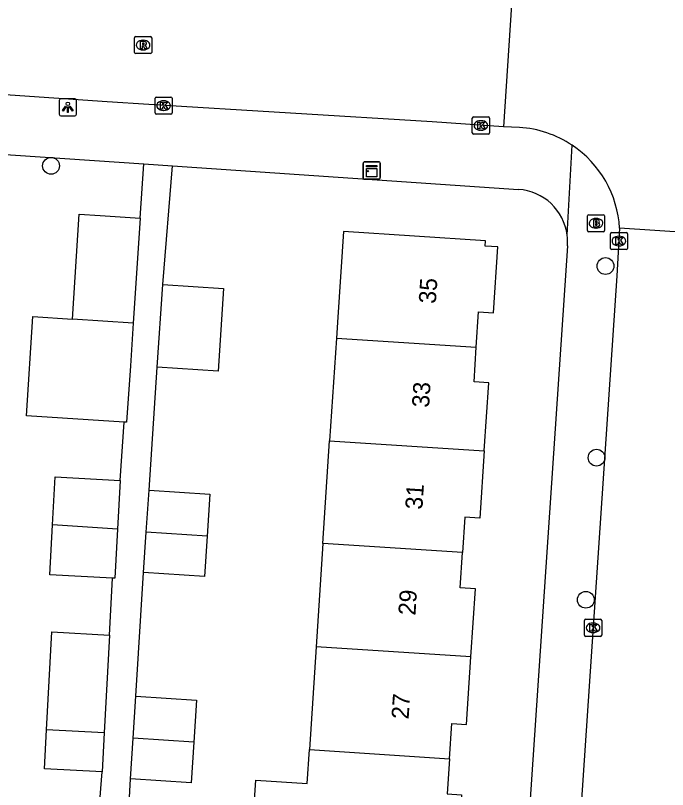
# Model space of a CAD drawing. Extents: x 161848 to 162726, y 385382 to 386521.
# Drawn here: x 162407.24 to 162445.21, y 385547.73 to 385592.78 of the extents above; entities that cross this region are included whole.
import ezdxf

# ---------------------------------------------------------------- set-up
doc = ezdxf.new("R2010")
doc.units = 0
for name, color, linetype in [('IMGEO_Boom', 7, 'Continuous'), ('IMGEO_Brandkraan', 7, 'Continuous'), ('IMGEO_Kast', 7, 'Continuous'), ('IMGEO_Kolk', 7, 'Continuous'), ('IMGEO_Lichtpunt', 7, 'Continuous'), ('IMGEO_Pand', 7, 'Continuous'), ('IMGEO_Pand_nummerreeks', 7, 'Continuous'), ('IMGEO_Rijbaan_lokaal_gesloten', 7, 'Continuous'), ('IMGEO_Rijbaan_lokaal_open', 7, 'Continuous'), ('IMGEO_Rioolput', 7, 'Continuous'), ('IMGEO_Voetpad_open', 7, 'Continuous')]:
    doc.layers.add(name, color=color, linetype=linetype)

msp = doc.modelspace()

# ---------------------------------------------------------------- linework, layer by layer
at = {"layer": 'IMGEO_Boom'}
for centre in [(162409.312, 385584.031), (162441.596, 385578.195), (162441.076, 385567.043), (162440.451, 385558.773)]:
    msp.add_circle(centre, 0.489, dxfattribs=at)
at = {"layer": 'IMGEO_Brandkraan'}
for p, q in [((162440.542, 385580.258), (162440.542, 385581.11)), ((162440.617, 385581.184), (162441.469, 385581.184)), ((162441.03, 385580.964), (162441.055, 385580.964)), ((162441.543, 385581.11), (162441.543, 385580.258)), ((162441.053, 385580.404), (162441.028, 385580.404)), ((162441.469, 385580.184), (162440.617, 385580.184))]:
    msp.add_line(p, q, dxfattribs=at)
for points in [[(162440.542, 385580.258), (162440.542, 385581.11)], [(162440.617, 385581.184), (162441.469, 385581.184)], [(162440.89, 385580.884), (162440.89, 385580.484), (162441.103, 385580.484)], [(162441.121, 385580.884), (162440.89, 385580.884)], [(162441.543, 385581.11), (162441.543, 385580.258)], [(162441.069, 385580.803), (162441.015, 385580.803), (162441.015, 385580.727)], [(162441.015, 385580.727), (162441.068, 385580.727)], [(162441.077, 385580.651), (162441.015, 385580.651), (162441.015, 385580.57)], [(162441.015, 385580.57), (162441.077, 385580.57)], [(162441.469, 385580.184), (162440.617, 385580.184)]]:
    msp.add_lwpolyline(points, dxfattribs=at)
for centre, radius, start, end in [((162440.619, 385581.108), 0.0765, 91.552, 178.448), ((162440.619, 385581.108), 0.0765, 91.552, 178.448), ((162441.125, 385580.739), 0.145, 59.4692, 91.5367), ((162441.15, 385580.786), 0.0922, 285.5137, 58.1501), ((162441.467, 385581.108), 0.0765, 1.552, 88.448), ((162441.467, 385581.108), 0.0765, 1.552, 88.448), ((162441.07, 385580.765), 0.0379, 267.8285, 90.9355), ((162441.078, 385580.61), 0.0404, 269.8759, 90.5077), ((162441.109, 385580.735), 0.251, 268.6676, 293.5347), ((162441.155, 385580.594), 0.105, 301.3115, 78.989), ((162440.619, 385580.26), 0.0765, 181.552, 268.448), ((162440.619, 385580.26), 0.0765, 181.552, 268.448), ((162441.467, 385580.26), 0.0765, 271.552, 358.448), ((162441.467, 385580.26), 0.0765, 271.552, 358.448)]:
    msp.add_arc(centre, radius, start, end, dxfattribs=at)
for centre, major_axis, ratio, start_param, end_param in [((162441.029, 385580.684), (-0.387, 0.002), 0.722429, 4.712389, 7.853982), ((162441.054, 385580.684), (-0.39, 0.002), 0.717154, 1.570796, 4.712389)]:
    msp.add_ellipse(centre, major_axis=major_axis, ratio=ratio, start_param=start_param, end_param=end_param, dxfattribs=at)
at = {"layer": 'IMGEO_Kast'}
for p, q in [((162427.478, 385583.332), (162427.478, 385584.173)), ((162427.478, 385584.173), (162427.478, 385583.332)), ((162427.553, 385584.257), (162428.394, 385584.257)), ((162428.394, 385584.257), (162427.553, 385584.257)), ((162428.478, 385584.182), (162428.478, 385583.341)), ((162428.478, 385583.341), (162428.478, 385584.182)), ((162428.403, 385583.257), (162427.562, 385583.257)), ((162427.562, 385583.257), (162428.403, 385583.257))]:
    msp.add_line(p, q, dxfattribs=at)
for points in [[(162427.673, 385584.047), (162428.273, 385584.047), (162428.273, 385583.962), (162427.673, 385583.962), (162427.673, 385584.047)], [(162427.673, 385583.872), (162428.273, 385583.872), (162428.273, 385583.383), (162427.673, 385583.383), (162427.673, 385583.872)]]:
    msp.add_lwpolyline(points, dxfattribs=at)
msp.add_circle((162427.757, 385583.721), 0.0377, dxfattribs=at)
for centre, start, end in [((162427.556, 385584.179), 92.4484, 184.2845), ((162427.556, 385584.179), 92.4484, 184.2845), ((162428.4, 385584.179), 2.4484, 94.2845), ((162428.4, 385584.179), 2.4484, 94.2845), ((162427.556, 385583.335), 182.4484, 274.2845), ((162427.556, 385583.335), 182.4484, 274.2845), ((162428.4, 385583.335), 272.4484, 4.2845), ((162428.4, 385583.335), 272.4484, 4.2845)]:
    msp.add_arc(centre, 0.0779, start, end, dxfattribs=at)
at = {"layer": 'IMGEO_Kolk'}
for p, q in [((162415.442, 385588.033), (162416.294, 385588.033)), ((162415.367, 385587.107), (162415.367, 385587.959)), ((162415.855, 385587.813), (162415.88, 385587.813)), ((162416.368, 385587.959), (162416.368, 385587.107)), ((162415.878, 385587.253), (162415.853, 385587.253)), ((162416.294, 385587.033), (162415.442, 385587.033)), ((162433.84, 385585.951), (162433.84, 385586.803)), ((162433.915, 385586.877), (162434.767, 385586.877)), ((162434.841, 385586.803), (162434.841, 385585.951)), ((162434.328, 385586.657), (162434.353, 385586.657)), ((162434.767, 385585.877), (162433.915, 385585.877)), ((162434.351, 385586.097), (162434.326, 385586.097)), ((162441.88, 385579.226), (162441.88, 385580.078)), ((162441.955, 385580.152), (162442.807, 385580.152)), ((162442.368, 385579.932), (162442.393, 385579.932)), ((162442.881, 385580.078), (162442.881, 385579.226)), ((162442.807, 385579.152), (162441.955, 385579.152)), ((162442.391, 385579.372), (162442.366, 385579.372)), ((162440.372, 385556.714), (162440.372, 385557.566)), ((162440.447, 385557.64), (162441.299, 385557.64)), ((162440.86, 385557.42), (162440.885, 385557.42)), ((162441.373, 385557.566), (162441.373, 385556.714)), ((162441.299, 385556.64), (162440.447, 385556.64)), ((162440.883, 385556.86), (162440.858, 385556.86))]:
    msp.add_line(p, q, dxfattribs=at)
for points in [[(162415.442, 385588.033), (162416.294, 385588.033)], [(162415.367, 385587.107), (162415.367, 385587.959)], [(162415.688, 385587.733), (162415.811, 385587.733), (162415.811, 385587.582), (162415.941, 385587.733), (162416.105, 385587.733), (162415.959, 385587.582), (162416.112, 385587.333), (162415.96, 385587.333), (162415.875, 385587.497), (162415.811, 385587.43), (162415.811, 385587.333), (162415.688, 385587.333), (162415.688, 385587.733)], [(162416.368, 385587.959), (162416.368, 385587.107)], [(162416.294, 385587.033), (162415.442, 385587.033)], [(162433.84, 385585.951), (162433.84, 385586.803)], [(162433.915, 385586.877), (162434.767, 385586.877)], [(162434.841, 385586.803), (162434.841, 385585.951)], [(162434.161, 385586.577), (162434.284, 385586.577), (162434.284, 385586.426), (162434.414, 385586.577), (162434.578, 385586.577), (162434.432, 385586.426), (162434.585, 385586.177), (162434.433, 385586.177), (162434.348, 385586.341), (162434.284, 385586.274), (162434.284, 385586.177), (162434.161, 385586.177), (162434.161, 385586.577)], [(162434.767, 385585.877), (162433.915, 385585.877)], [(162441.88, 385579.226), (162441.88, 385580.078)], [(162441.955, 385580.152), (162442.807, 385580.152)], [(162442.881, 385580.078), (162442.881, 385579.226)], [(162442.201, 385579.852), (162442.324, 385579.852), (162442.324, 385579.701), (162442.454, 385579.852), (162442.618, 385579.852), (162442.472, 385579.701), (162442.625, 385579.452), (162442.473, 385579.452), (162442.388, 385579.616), (162442.324, 385579.549), (162442.324, 385579.452), (162442.201, 385579.452), (162442.201, 385579.852)], [(162442.807, 385579.152), (162441.955, 385579.152)], [(162440.372, 385556.714), (162440.372, 385557.566)], [(162440.447, 385557.64), (162441.299, 385557.64)], [(162441.373, 385557.566), (162441.373, 385556.714)], [(162440.693, 385557.34), (162440.816, 385557.34), (162440.816, 385557.189), (162440.946, 385557.34), (162441.11, 385557.34), (162440.964, 385557.189), (162441.117, 385556.94), (162440.965, 385556.94), (162440.88, 385557.104), (162440.816, 385557.037), (162440.816, 385556.94), (162440.693, 385556.94), (162440.693, 385557.34)], [(162441.299, 385556.64), (162440.447, 385556.64)]]:
    msp.add_lwpolyline(points, dxfattribs=at)
for centre, start, end in [((162415.444, 385587.957), 91.552, 178.448), ((162415.444, 385587.957), 91.552, 178.448), ((162416.292, 385587.957), 1.552, 88.448), ((162416.292, 385587.957), 1.552, 88.448), ((162415.444, 385587.109), 181.552, 268.448), ((162415.444, 385587.109), 181.552, 268.448), ((162416.292, 385587.109), 271.552, 358.448), ((162416.292, 385587.109), 271.552, 358.448), ((162433.917, 385586.801), 91.552, 178.448), ((162433.917, 385586.801), 91.552, 178.448), ((162434.765, 385586.801), 1.552, 88.448), ((162434.765, 385586.801), 1.552, 88.448), ((162433.917, 385585.953), 181.552, 268.448), ((162433.917, 385585.953), 181.552, 268.448), ((162434.765, 385585.953), 271.552, 358.448), ((162434.765, 385585.953), 271.552, 358.448), ((162441.957, 385580.076), 91.552, 178.448), ((162441.957, 385580.076), 91.552, 178.448), ((162442.805, 385580.076), 1.552, 88.448), ((162442.805, 385580.076), 1.552, 88.448), ((162441.957, 385579.228), 181.552, 268.448), ((162441.957, 385579.228), 181.552, 268.448), ((162442.805, 385579.228), 271.552, 358.448), ((162442.805, 385579.228), 271.552, 358.448), ((162440.449, 385557.564), 91.552, 178.448), ((162440.449, 385557.564), 91.552, 178.448), ((162441.297, 385557.564), 1.552, 88.448), ((162441.297, 385557.564), 1.552, 88.448), ((162440.449, 385556.716), 181.552, 268.448), ((162440.449, 385556.716), 181.552, 268.448), ((162441.297, 385556.716), 271.552, 358.448), ((162441.297, 385556.716), 271.552, 358.448)]:
    msp.add_arc(centre, 0.0765, start, end, dxfattribs=at)
for centre, major_axis, ratio, start_param, end_param in [((162415.854, 385587.533), (-0.387, 0.002), 0.722429, 4.712389, 7.853982), ((162415.879, 385587.533), (-0.39, 0.002), 0.717154, 1.570796, 4.712389), ((162434.327, 385586.377), (-0.387, 0.002), 0.722429, 4.712389, 7.853982), ((162434.352, 385586.377), (-0.39, 0.002), 0.717154, 1.570796, 4.712389), ((162442.367, 385579.652), (-0.387, 0.002), 0.722429, 4.712389, 7.853982), ((162442.392, 385579.652), (-0.39, 0.002), 0.717154, 1.570796, 4.712389), ((162440.859, 385557.14), (-0.387, 0.002), 0.722429, 4.712389, 7.853982), ((162440.884, 385557.14), (-0.39, 0.002), 0.717154, 1.570796, 4.712389)]:
    msp.add_ellipse(centre, major_axis=major_axis, ratio=ratio, start_param=start_param, end_param=end_param, dxfattribs=at)
at = {"layer": 'IMGEO_Lichtpunt'}
for p, q in [((162409.789, 385587.84), (162409.789, 385587.033)), ((162409.789, 385587.84), (162409.789, 385587.033)), ((162410.691, 385587.935), (162409.883, 385587.935)), ((162410.691, 385587.935), (162409.883, 385587.935)), ((162410.785, 385587.033), (162410.785, 385587.84)), ((162410.785, 385587.033), (162410.785, 385587.84)), ((162409.883, 385586.939), (162410.691, 385586.939)), ((162409.883, 385586.939), (162410.691, 385586.939))]:
    msp.add_line(p, q, dxfattribs=at)
for points in [[(162410.163, 385587.504), (162410.202, 385587.476), (162410.014, 385587.214), (162409.976, 385587.241), (162410.163, 385587.504)], [(162410.265, 385587.456), (162410.312, 385587.456), (162410.312, 385587.134), (162410.265, 385587.134), (162410.265, 385587.456)], [(162410.375, 385587.476), (162410.413, 385587.503), (162410.6, 385587.241), (162410.561, 385587.213), (162410.375, 385587.476)]]:
    msp.add_lwpolyline(points, dxfattribs=at)
msp.add_circle((162410.288, 385587.638), 0.0994, dxfattribs=at)
for centre, start, end in [((162409.883, 385587.84), 90, 180), ((162409.883, 385587.84), 90, 180), ((162410.691, 385587.84), 0, 90), ((162410.691, 385587.84), 0, 90), ((162409.883, 385587.033), 180, 270), ((162409.883, 385587.033), 180, 270), ((162410.691, 385587.033), 270, 0), ((162410.691, 385587.033), 270, 360)]:
    msp.add_arc(centre, 0.0946, start, end, dxfattribs=at)
at = {"layer": 'IMGEO_Pand'}
for points in [[(162410.552, 385575.105), (162410.959, 385581.223), (162412.172, 385581.142), (162414.505, 385580.987)], [(162414.505, 385580.987), (162414.099, 385574.88)], [(162434.075, 385573.479), (162434.21, 385575.526), (162435.077, 385575.469), (162435.33, 385579.306), (162434.586, 385579.355), (162434.606, 385579.658), (162426.336, 385580.201), (162426.009, 385575.222), (162425.929, 385574.004)], [(162415.498, 385572.314), (162415.817, 385577.119)], [(162415.817, 385577.119), (162419.358, 385576.884), (162419.039, 385572.079), (162415.498, 385572.314)], [(162413.561, 385569.117), (162407.876, 385569.477), (162408.242, 385575.251), (162410.552, 385575.105)], [(162414.099, 385574.88), (162410.552, 385575.105)], [(162414.099, 385574.88), (162413.933, 385572.382), (162413.715, 385569.107), (162413.561, 385569.117)], [(162425.929, 385574.004), (162425.535, 385568.02)], [(162425.929, 385574.004), (162434.075, 385573.479)], [(162434.539, 385567.438), (162434.8, 385571.4), (162433.942, 385571.457), (162434.075, 385573.479)], [(162425.142, 385562.045), (162425.535, 385568.02)], [(162425.535, 385568.02), (162434.539, 385567.438)], [(162434.539, 385567.438), (162434.282, 385563.522), (162433.412, 385563.579), (162433.276, 385561.52)], [(162409.401, 385563.129), (162409.554, 385565.925), (162413.336, 385565.718)], [(162413.336, 385565.718), (162413.181, 385562.874)], [(162414.855, 385562.709), (162415.018, 385565.16)], [(162415.018, 385565.16), (162418.559, 385564.925), (162418.397, 385562.48)], [(162412.899, 385560.029), (162409.243, 385560.228), (162409.401, 385563.129)], [(162413.181, 385562.874), (162409.401, 385563.129)], [(162413.181, 385562.874), (162413.025, 385560.022), (162412.899, 385560.029)], [(162414.699, 385560.355), (162414.855, 385562.709)], [(162418.397, 385562.48), (162418.24, 385560.12), (162414.699, 385560.355)], [(162418.397, 385562.48), (162414.855, 385562.709)], [(162425.142, 385562.045), (162424.746, 385556.037)], [(162433.276, 385561.52), (162425.142, 385562.045)], [(162433.76, 385555.455), (162434.02, 385559.403), (162433.14, 385559.461), (162433.276, 385561.52)], [(162409.049, 385551.203), (162409.36, 385556.9), (162412.719, 385556.716)], [(162412.719, 385556.716), (162412.408, 385551.02)], [(162424.746, 385556.037), (162424.352, 385550.049)], [(162433.76, 385555.455), (162424.746, 385556.037)], [(162432.506, 385549.522), (162432.64, 385551.564), (162433.5, 385551.507), (162433.76, 385555.455)], [(162414.085, 385550.713), (162414.248, 385553.162)], [(162414.248, 385553.162), (162417.789, 385552.927), (162417.627, 385550.484)], [(162412.284, 385548.754), (162408.925, 385548.938), (162409.049, 385551.203)], [(162412.408, 385551.02), (162409.049, 385551.203)], [(162412.408, 385551.02), (162412.284, 385548.754)], [(162413.929, 385548.357), (162414.085, 385550.713)], [(162417.627, 385550.484), (162414.085, 385550.713)], [(162417.627, 385550.484), (162417.47, 385548.122), (162413.929, 385548.357)], [(162420.863, 385542.71), (162421.229, 385548.269), (162424.222, 385548.072), (162424.352, 385550.049)], [(162424.352, 385550.049), (162432.506, 385549.522)], [(162432.506, 385549.522), (162432.371, 385547.479), (162433.217, 385547.423), (162432.948, 385543.326), (162431.81, 385543.401)]]:
    msp.add_lwpolyline(points, dxfattribs=at)
at = {"layer": 'IMGEO_Rijbaan_lokaal_gesloten'}
msp.add_lwpolyline([(162442.418, 385580.396), (162442.248, 385577.631), (162439.944, 385543.379), (162439.699, 385539.748), (162437.017, 385500), (162434.834, 385467.105)], dxfattribs=at)
at = {"layer": 'IMGEO_Rijbaan_lokaal_open'}
for points in [[(162436.128, 385593.403), (162435.655, 385586.297)], [(162435.655, 385586.297), (162431.505, 385586.582), (162415.011, 385587.593), (162412.585, 385587.758), (162392.515, 385589.122)], [(162436.585, 385586.264), (162435.655, 385586.297)], [(162450.352, 385579.883), (162442.418, 385580.396)]]:
    msp.add_lwpolyline(points, dxfattribs=at)
for centre, radius, start, end in [((162436.192, 385580.038), 6.238, 56.2651, 86.3843), ((162436.195, 385580.042), 6.233, 3.2533, 56.2722)]:
    msp.add_arc(centre, radius, start, end, dxfattribs=at)
at = {"layer": 'IMGEO_Rioolput'}
for p, q in [((162414.171, 385590.632), (162414.171, 385591.484)), ((162414.246, 385591.558), (162415.098, 385591.558)), ((162414.659, 385591.338), (162414.684, 385591.338)), ((162415.172, 385591.484), (162415.172, 385590.632)), ((162414.682, 385590.778), (162414.657, 385590.778)), ((162415.098, 385590.558), (162414.246, 385590.558))]:
    msp.add_line(p, q, dxfattribs=at)
for points in [[(162414.171, 385590.632), (162414.171, 385591.484)], [(162414.246, 385591.558), (162415.098, 385591.558)], [(162414.76, 385591.256), (162414.508, 385591.258), (162414.508, 385590.858)], [(162415.172, 385591.484), (162415.172, 385590.632)], [(162414.508, 385590.858), (162414.632, 385590.858), (162414.632, 385591.02), (162414.643, 385591.02)], [(162414.686, 385591.177), (162414.632, 385591.177), (162414.632, 385591.096)], [(162414.632, 385591.096), (162414.684, 385591.096)], [(162414.69, 385590.991), (162414.761, 385590.858), (162414.901, 385590.858), (162414.836, 385590.984)], [(162415.098, 385590.558), (162414.246, 385590.558)]]:
    msp.add_lwpolyline(points, dxfattribs=at)
for centre, radius, start, end in [((162414.248, 385591.482), 0.0765, 91.552, 178.448), ((162414.248, 385591.482), 0.0765, 91.552, 178.448), ((162414.759, 385591.146), 0.109, 350.3612, 89.416), ((162415.096, 385591.482), 0.0765, 1.552, 88.448), ((162415.096, 385591.482), 0.0765, 1.552, 88.448), ((162414.642, 385590.967), 0.0533, 26.0293, 88.6989), ((162414.668, 385591.285), 0.19, 274.7715, 282.9687), ((162414.692, 385591.081), 0.0964, 77.0061, 93.1865), ((162414.706, 385591.138), 0.0378, 276.6634, 79.6772), ((162414.757, 385591.146), 0.112, 277.5842, 350.9817), ((162414.741, 385590.931), 0.108, 29.5134, 73.7905), ((162414.248, 385590.634), 0.0765, 181.552, 268.448), ((162414.248, 385590.634), 0.0765, 181.552, 268.448), ((162415.096, 385590.634), 0.0765, 271.552, 358.448), ((162415.096, 385590.634), 0.0765, 271.552, 358.448)]:
    msp.add_arc(centre, radius, start, end, dxfattribs=at)
for centre, major_axis, ratio, start_param, end_param in [((162414.658, 385591.058), (-0.387, 0.002), 0.722429, 4.712389, 7.853982), ((162414.683, 385591.058), (-0.39, 0.002), 0.717154, 1.570796, 4.712389)]:
    msp.add_ellipse(centre, major_axis=major_axis, ratio=ratio, start_param=start_param, end_param=end_param, dxfattribs=at)
at = {"layer": 'IMGEO_Voetpad_open'}
for points in [[(162439.366, 385579.99), (162439.656, 385585.226)], [(162404.051, 385584.872), (162414.714, 385584.138)], [(162414.505, 385580.987), (162414.714, 385584.138)], [(162414.714, 385584.138), (162416.391, 385584.025)], [(162415.817, 385577.119), (162416.391, 385584.025)], [(162416.391, 385584.025), (162436.53, 385582.66)], [(162439.383, 385579.377), (162434.023, 385500), (162431.842, 385467.698), (162431.712, 385465.708)], [(162415.018, 385565.16), (162415.498, 385572.314)], [(162413.336, 385565.718), (162413.561, 385569.117)], [(162414.248, 385553.162), (162414.699, 385560.355)], [(162412.719, 385556.716), (162412.899, 385560.029)], [(162411.454, 385538.275), (162412.284, 385548.754)], [(162413.028, 385532.334), (162413.235, 385535.449), (162413.929, 385548.357)]]:
    msp.add_lwpolyline(points, dxfattribs=at)
for centre, radius, start, end in [((162436.32, 385579.596), 3.071, 7.3682, 86.0855), ((162436.352, 385579.6), 3.039, 355.7977, 7.3793)]:
    msp.add_arc(centre, radius, start, end, dxfattribs=at)

# ---------------------------------------------------------------- texts
at = {"layer": 'IMGEO_Pand_nummerreeks'}
for s, p in [('35', (162431.715, 385575.983)), ('33', (162431.319, 385569.936)), ('31', (162430.929, 385564.001)), ('29', (162430.526, 385557.841)), ('27', (162430.129, 385551.794))]:
    msp.add_text(s, height=1, rotation=86.2486, dxfattribs=at).set_placement(p)

doc.saveas('drawing.dxf')
